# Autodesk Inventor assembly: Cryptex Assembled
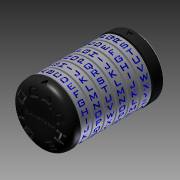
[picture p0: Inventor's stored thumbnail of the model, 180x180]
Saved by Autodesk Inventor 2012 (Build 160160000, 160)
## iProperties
Created: 2012-04
Part Number: Cryptex Assembled
Document SubType Name: Assembly
Designer: Pierce
Mass: 203.239 g
Surface Area: 1163.33 cm^2
Volume: 194.253 cm^3
Density: 1.04626 g/cm^3
Author: Pierce
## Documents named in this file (9)
- C:\Users\Pierce\Documents\FIRST Robotics\Cryptex\Cryptex Assembled.iam
- C:\Users\Pierce\Documents\FIRST Robotics\Cryptex\Cryptex Interior Chamber.ipt
- C:\Users\Pierce\Documents\FIRST Robotics\Cryptex\Cryptex Outer Chamber.ipt
- C:\Users\Pierce\Documents\FIRST Robotics\Cryptex\Rings\Cryptex Ring 1.ipt
- C:\Users\Pierce\Documents\FIRST Robotics\Cryptex\Rings\Cryptex Ring 2.ipt
- C:\Users\Pierce\Documents\FIRST Robotics\Cryptex\Rings\Cryptex Ring 3.ipt
- C:\Users\Pierce\Documents\FIRST Robotics\Cryptex\Rings\Cryptex Ring 4.ipt
- C:\Users\Pierce\Documents\FIRST Robotics\Cryptex\Rings\Cryptex Ring 5.ipt
- C:\Users\Pierce\Documents\FIRST Robotics\Cryptex\Rings\Cryptex Ring 6.ipt
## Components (8 placed, 8 different names)
1. Cryptex Outer Chamber:1 — Mate:1, Angle:1, Mate:2, Angle:2, Flush:1, Mate:3, Mate:4, Mate:5, Angle:3, Mate:6, Angle:4, Mate:7, Mate:8, Angle:5, Mate:9, Mate:10, Angle:6, Mate:11, Angle:7, Mate:13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
2. Cryptex Interior Chamber:2 — Mate:5, Angle:3, Mate:6
3. Cryptex Ring 1:1 — Mate:1, Angle:1, Mate:2
4. Cryptex Ring 2:1 — Angle:2, Mate:3, Mate:4
5. Cryptex Ring 3:1 — Angle:4, Mate:7, Mate:8
6. Cryptex Ring 4:1 — Angle:5, Mate:9, Mate:10
7. Cryptex Ring 5:1 — Angle:6, Mate:11, Mate:15
8. Cryptex Ring 6:1 — Angle:7, Mate:13, Mate:14
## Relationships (23: Mate 15, Angle 7, Flush 1)
- Mate:1: Cryptex Outer Chamber:1 ↔ Cryptex Ring 1:1
- Angle:1: Cryptex Outer Chamber:1 ↔ Cryptex Ring 1:1
- Mate:2: Cryptex Outer Chamber:1 ↔ Cryptex Ring 1:1
- Angle:2: Cryptex Outer Chamber:1 ↔ Cryptex Ring 2:1
- Flush:1: Cryptex Outer Chamber:1
- Mate:3: Cryptex Outer Chamber:1 ↔ Cryptex Ring 2:1
- Mate:4: Cryptex Outer Chamber:1 ↔ Cryptex Ring 2:1
- Mate:5: Cryptex Outer Chamber:1 ↔ Cryptex Interior Chamber:2
- Angle:3: Cryptex Outer Chamber:1 ↔ Cryptex Interior Chamber:2
- Mate:6: Cryptex Outer Chamber:1 ↔ Cryptex Interior Chamber:2
- Angle:4: Cryptex Outer Chamber:1 ↔ Cryptex Ring 3:1
- Mate:7: Cryptex Outer Chamber:1 ↔ Cryptex Ring 3:1
- Mate:8: Cryptex Outer Chamber:1 ↔ Cryptex Ring 3:1
- Angle:5: Cryptex Outer Chamber:1 ↔ Cryptex Ring 4:1
- Mate:9: Cryptex Outer Chamber:1 ↔ Cryptex Ring 4:1
- Mate:10: Cryptex Outer Chamber:1 ↔ Cryptex Ring 4:1
- Angle:6: Cryptex Outer Chamber:1 ↔ Cryptex Ring 5:1
- Mate:11: Cryptex Outer Chamber:1 ↔ Cryptex Ring 5:1
- Angle:7: Cryptex Outer Chamber:1 ↔ Cryptex Ring 6:1
- Mate:13: Cryptex Outer Chamber:1 ↔ Cryptex Ring 6:1
- Mate:14: Cryptex Outer Chamber:1 ↔ Cryptex Ring 6:1
- Mate:15: Cryptex Outer Chamber:1 ↔ Cryptex Ring 5:1
- Mate:16: Cryptex Outer Chamber:1
